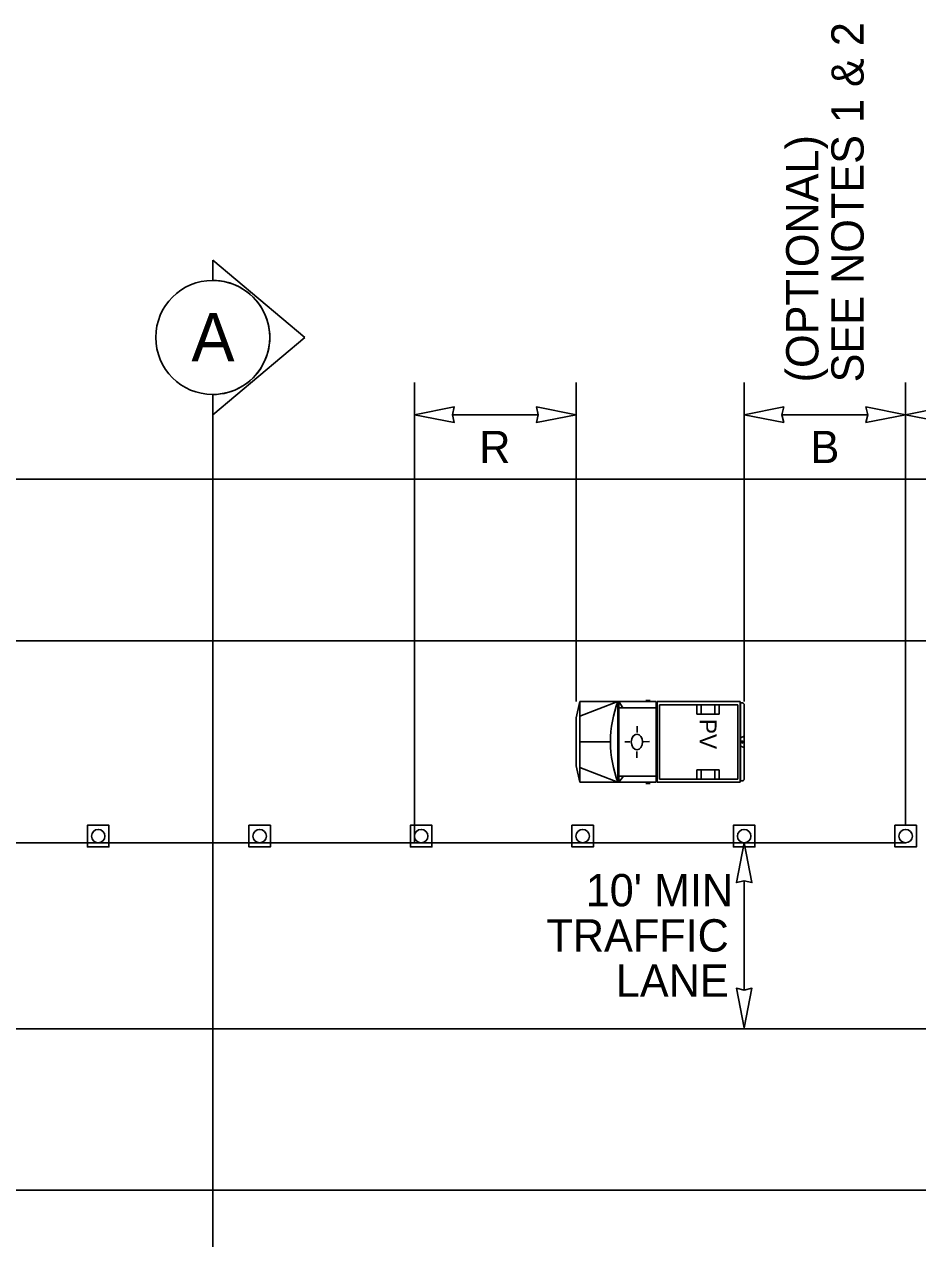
# Model space of a CAD drawing. Extents: x 99999.1 to 100095.7, y 99995 to 100010.7.
# Drawn here: x 100008.967 to 100011.18, y 100005.612 to 100008.619 of the extents above; entities that cross this region are included whole.
import ezdxf

# ---------------------------------------------------------------- set-up
doc = ezdxf.new("R2010")
doc.units = 0
for name, color, linetype in [('RD_ED_ShoulderPavedEdge', 7, 'Continuous'), ('RD_MK_LineEdgeWhite', 7, 'Continuous'), ('RD_MK_LineSkipCenter', 7, 'Continuous'), ('SH_TI_WZSectionCut', 7, 'Continuous'), ('TR_WZ_ProtectiveVehicle', 7, 'Continuous'), ('TR_WZ_TrafficCone', 7, 'Continuous'), ('TR_WZ_WorkZoneDetails', 7, 'Continuous'), ('TR_WZ_WorkZoneTextCurrent', 7, 'Continuous')]:
    doc.layers.add(name, color=color, linetype=linetype)

msp = doc.modelspace()

# ---------------------------------------------------------------- linework, layer by layer
at = {"layer": 'RD_ED_ShoulderPavedEdge'}
for p, q in [((100000.1076, 100007.4923), (100015.6424, 100007.4923)), ((100000.1076, 100005.7323), (100015.6424, 100005.7323))]:
    msp.add_line(p, q, dxfattribs=at)
at = {"layer": 'RD_MK_LineEdgeWhite'}
for p, q in [((100000.1076, 100007.0923), (100015.6424, 100007.0923)), ((100000.1076, 100006.1323), (100015.6424, 100006.1323))]:
    msp.add_line(p, q, dxfattribs=at)
at = {"layer": 'RD_MK_LineSkipCenter'}
msp.add_lwpolyline([(100011.15, 100006.5923), (100003.4767, 100006.5923)], dxfattribs=at)
at = {"layer": 'SH_TI_WZSectionCut'}
for p, q in [((100009.4337, 100007.9847), (100009.4337, 100008.0346)), ((100009.4337, 100008.0346), (100009.6619, 100007.8435)), ((100009.6619, 100007.8435), (100009.4337, 100007.6523)), ((100009.4337, 100007.6523), (100009.4337, 100007.7022)), ((100009.4338, 100007.7022), (100009.4338, 100005.5723))]:
    msp.add_line(p, q, dxfattribs=at)
msp.add_circle((100009.4338, 100007.8435), 0.1412, dxfattribs=at)
msp.add_arc((100009.4338, 100007.8435), 0.1412, 269.9978, 90.0022, dxfattribs=at)
at = {"layer": 'TR_WZ_ProtectiveVehicle'}
for p, q in [((100010.343, 100006.9423), (100010.3338, 100006.902)), ((100010.343, 100006.7423), (100010.343, 100006.9423)), ((100010.343, 100006.9423), (100010.5319, 100006.9423)), ((100010.343, 100006.9057), (100010.4375, 100006.9423)), ((100010.4375, 100006.7423), (100010.4375, 100006.9423)), ((100010.4392, 100006.7423), (100010.4392, 100006.9423)), ((100010.4492, 100006.9268), (100010.4392, 100006.9423)), ((100010.5062, 100006.9451), (100010.5175, 100006.9451)), ((100010.5319, 100006.7423), (100010.5319, 100006.9423)), ((100010.7404, 100006.9423), (100010.5347, 100006.9423)), ((100010.5347, 100006.7423), (100010.5347, 100006.9423)), ((100010.7404, 100006.7423), (100010.7404, 100006.9423)), ((100010.4392, 100006.9268), (100010.5319, 100006.9268)), ((100010.7346, 100006.9344), (100010.5405, 100006.9344)), ((100010.5405, 100006.7503), (100010.5405, 100006.9344)), ((100010.6332, 100006.9344), (100010.6332, 100006.9113)), ((100010.6882, 100006.9113), (100010.6332, 100006.9113)), ((100010.6432, 100006.9344), (100010.6432, 100006.9113)), ((100010.6772, 100006.9344), (100010.6772, 100006.9113)), ((100010.6882, 100006.9344), (100010.6882, 100006.9113)), ((100010.7346, 100006.7503), (100010.7346, 100006.9344)), ((100010.7456, 100006.939), (100010.7411, 100006.939)), ((100010.7411, 100006.7456), (100010.7411, 100006.939)), ((100010.75, 100006.7517), (100010.75, 100006.9329)), ((100010.3338, 100006.7827), (100010.3338, 100006.902)), ((100010.4852, 100006.8808), (100010.485, 100006.8658)), ((100010.75, 100006.8564), (100010.7411, 100006.8527)), ((100010.343, 100006.8423), (100010.4189, 100006.8423)), ((100010.4544, 100006.8422), (100010.467, 100006.8423)), ((100010.4986, 100006.8427), (100010.4986, 100006.8427)), ((100010.5154, 100006.8431), (100010.5005, 100006.8427)), ((100010.75, 100006.8282), (100010.7411, 100006.832)), ((100010.7476, 100006.8423), (100010.7435, 100006.8423)), ((100010.7456, 100006.8395), (100010.7456, 100006.8451)), ((100010.4845, 100006.8027), (100010.4845, 100006.8188)), ((100010.343, 100006.7423), (100010.3338, 100006.7827)), ((100010.343, 100006.779), (100010.4375, 100006.7423)), ((100010.6882, 100006.7733), (100010.6332, 100006.7733)), ((100010.6332, 100006.7503), (100010.6332, 100006.7733)), ((100010.6432, 100006.7503), (100010.6432, 100006.7733)), ((100010.6772, 100006.7503), (100010.6772, 100006.7733)), ((100010.6882, 100006.7503), (100010.6882, 100006.7733)), ((100010.343, 100006.7423), (100010.5319, 100006.7423)), ((100010.4392, 100006.7423), (100010.4512, 100006.7578)), ((100010.4392, 100006.7578), (100010.5319, 100006.7578)), ((100010.5062, 100006.7395), (100010.5175, 100006.7395)), ((100010.7404, 100006.7423), (100010.5347, 100006.7423)), ((100010.7346, 100006.7503), (100010.5405, 100006.7503)), ((100010.7456, 100006.7456), (100010.7411, 100006.7456))]:
    msp.add_line(p, q, dxfattribs=at)
for centre, major_axis, start_param, end_param in [((100010.5725, 100006.8424), (0, -0.2099), 4.215852, 5.209111), ((100010.7456, 100006.9329), (0, 0.0061), 4.712389, 6.283185), ((100010.7456, 100006.7517), (0, -0.0061), 6.283185, 7.853982)]:
    msp.add_ellipse(centre, major_axis=major_axis, ratio=0.73155, start_param=start_param, end_param=end_param, dxfattribs=at)
for centre, major_axis in [((100010.4845, 100006.8423), (0, 0.0193)), ((100010.7456, 100006.8423), (0, 0.00282))]:
    msp.add_ellipse(centre, major_axis=major_axis, ratio=0.73155, dxfattribs=at)
at = {"layer": 'TR_WZ_TrafficCone'}
for points in [[(100009.1234, 100006.6357), (100009.1767, 100006.6357), (100009.1767, 100006.5823), (100009.1234, 100006.5823), (100009.1234, 100006.6357)], [(100009.1234, 100006.5823), (100009.1767, 100006.5823), (100009.1767, 100006.6357), (100009.1234, 100006.6357), (100009.1234, 100006.5823)], [(100009.5234, 100006.6357), (100009.5767, 100006.6357), (100009.5767, 100006.5823), (100009.5234, 100006.5823), (100009.5234, 100006.6357)], [(100009.5234, 100006.5823), (100009.5767, 100006.5823), (100009.5767, 100006.6357), (100009.5234, 100006.6357), (100009.5234, 100006.5823)], [(100009.9234, 100006.6357), (100009.9767, 100006.6357), (100009.9767, 100006.5823), (100009.9234, 100006.5823), (100009.9234, 100006.6357)], [(100009.9234, 100006.5823), (100009.9767, 100006.5823), (100009.9767, 100006.6357), (100009.9234, 100006.6357), (100009.9234, 100006.5823)], [(100010.3234, 100006.6357), (100010.3767, 100006.6357), (100010.3767, 100006.5823), (100010.3234, 100006.5823), (100010.3234, 100006.6357)], [(100010.3234, 100006.5823), (100010.3767, 100006.5823), (100010.3767, 100006.6357), (100010.3234, 100006.6357), (100010.3234, 100006.5823)], [(100010.7234, 100006.6357), (100010.7767, 100006.6357), (100010.7767, 100006.5823), (100010.7234, 100006.5823), (100010.7234, 100006.6357)], [(100010.7234, 100006.5823), (100010.7767, 100006.5823), (100010.7767, 100006.6357), (100010.7234, 100006.6357), (100010.7234, 100006.5823)], [(100011.1766, 100006.6357), (100011.1233, 100006.6357), (100011.1233, 100006.5823), (100011.1766, 100006.5823), (100011.1766, 100006.6357)], [(100011.1766, 100006.5823), (100011.1233, 100006.5823), (100011.1233, 100006.6357), (100011.1766, 100006.6357), (100011.1766, 100006.5823)]]:
    msp.add_lwpolyline(points, dxfattribs=at)
for centre in [(100009.15, 100006.609), (100009.55, 100006.609), (100009.95, 100006.609), (100010.35, 100006.609), (100010.75, 100006.609), (100011.15, 100006.609)]:
    msp.add_circle(centre, 0.0167, dxfattribs=at)
at = {"layer": 'TR_WZ_WorkZoneDetails'}
for p, q in [((100009.9338, 100007.4923), (100009.9338, 100007.7323)), ((100010.3338, 100006.9423), (100010.3338, 100007.7323)), ((100010.75, 100006.9423), (100010.75, 100007.7323)), ((100011.15, 100006.6357), (100011.15, 100007.7323)), ((100010.24, 100007.6523), (100010.0275, 100007.6523)), ((100011.0563, 100007.6523), (100010.8437, 100007.6523)), ((100010.75, 100006.2278), (100010.75, 100006.4986))]:
    msp.add_line(p, q, dxfattribs=at)
for points in [[(100009.9338, 100007.6523), (100010.032, 100007.6331), (100010.0275, 100007.6523), (100010.032, 100007.6716)], [(100010.3338, 100007.6523), (100010.2355, 100007.6331), (100010.24, 100007.6523), (100010.2355, 100007.6716)], [(100010.75, 100007.6523), (100010.8483, 100007.6331), (100010.8437, 100007.6523), (100010.8483, 100007.6716)], [(100011.15, 100007.6523), (100011.0517, 100007.6331), (100011.0563, 100007.6523), (100011.0517, 100007.6716)], [(100011.15, 100007.6523), (100011.2483, 100007.6331), (100011.2437, 100007.6523), (100011.2483, 100007.6716)], [(100005.15, 100007.4923), (100005.15, 100006.5923), (100009.9338, 100006.5923), (100009.9338, 100007.4923)], [(100010.75, 100006.5923), (100010.7308, 100006.4941), (100010.75, 100006.4986), (100010.7693, 100006.4941)], [(100010.75, 100006.1341), (100010.7308, 100006.2324), (100010.75, 100006.2278), (100010.7693, 100006.2324)]]:
    msp.add_lwpolyline(points, close=True, dxfattribs=at)

# ---------------------------------------------------------------- texts
at = {"layer": 'SH_TI_WZSectionCut'}
msp.add_text('A', height=0.12, rotation=359.99, dxfattribs=at).set_placement((100009.3808, 100007.7843))
at = {"layer": 'TR_WZ_ProtectiveVehicle'}
msp.add_text('PV', height=0.04175, rotation=270, dxfattribs=at).set_placement((100010.6398, 100006.899))
at = {"layer": 'TR_WZ_WorkZoneTextCurrent'}
for s, p in [('SEE NOTES 1 & 2', (100011.046, 100007.7323)), ('(OPTIONAL)', (100010.934, 100007.7323))]:
    msp.add_text(s, height=0.08, rotation=90, dxfattribs=at).set_placement(p)
for s, p in [('R', (100010.0939, 100007.5323)), ('B', (100010.9145, 100007.5323)), ("10' MIN", (100010.3575, 100006.4352)), ('TRAFFIC', (100010.2604, 100006.3232)), ('LANE', (100010.4323, 100006.2112))]:
    msp.add_text(s, height=0.08, dxfattribs=at).set_placement(p)

doc.saveas('drawing.dxf')
